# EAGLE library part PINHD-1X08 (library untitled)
PIN HEADER
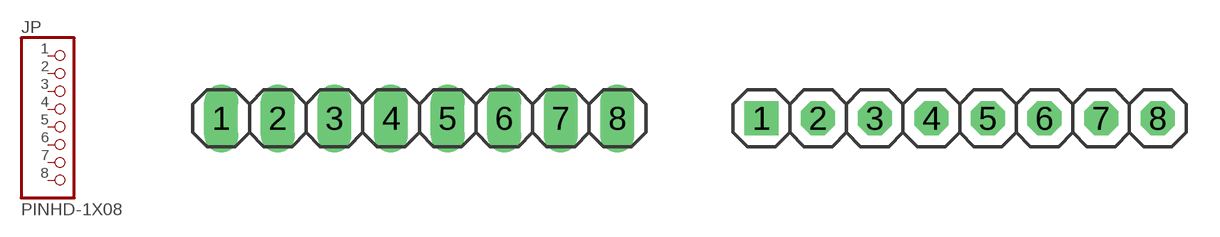
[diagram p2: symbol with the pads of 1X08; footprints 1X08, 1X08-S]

Designator prefix JP

## PINHD-1X08_2.54  [1X08]
1  1  pas
2  2  pas
3  3  pas
4  4  pas
5  5  pas
6  6  pas
7  7  pas
8  8  pas

## PINHD-1X08_2.54-S  [1X08-S]
Pads as for 1X08

## PINHD-1X08_2.54-90°  [1X08/90]
Pads as for 1X08

## PINHD-1X08_2.54-90°-S  [1X08/90-S]
Pads as for 1X08

## PINHD-1X08_2.00  [1X08M]
Pads as for 1X08

## PINHD-1X08_2.54-SMD  [1X08SMD]
Pads as for 1X08

## PINHD-1X08_2.54-SMD-90°  [1X08SMD/90]
Pads as for 1X08

## Footprint 1X08 (pad centres in mm)
PIN HEADER - 2.54
drill 1.016 long: 1 -8.89,0; 2 -6.35,0; 3 -3.81,0; 4 -1.27,0; 5 1.27,0; 6 3.81,0; 7 6.35,0; 8 8.89,0

## Footprint 1X08-S (pad centres in mm)
PIN HEADER - 2.54
drill 1.016 square: 1 -8.89,0
drill 1.016 octagon: 2 -6.35,0; 3 -3.81,0; 4 -1.27,0; 5 1.27,0; 6 3.81,0; 7 6.35,0; 8 8.89,0

## Footprint 1X08/90 (pad centres in mm)
PIN HEADER - 2.54 90°
drill 1.016 long: 1 -8.89,-3.81; 2 -6.35,-3.81; 3 -3.81,-3.81; 4 -1.27,-3.81; 5 1.27,-3.81; 6 3.81,-3.81; 7 6.35,-3.81; 8 8.89,-3.81

## Footprint 1X08/90-S (pad centres in mm)
PIN HEADER - 2.54 90°
drill 1.016 square: 1 -8.89,-3.81
drill 1.016 octagon: 2 -6.35,-3.81; 3 -3.81,-3.81; 4 -1.27,-3.81; 5 1.27,-3.81; 6 3.81,-3.81; 7 6.35,-3.81; 8 8.89,-3.81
